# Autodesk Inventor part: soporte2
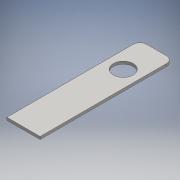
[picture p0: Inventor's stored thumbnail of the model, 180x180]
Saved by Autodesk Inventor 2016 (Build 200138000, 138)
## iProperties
Created: 2016-06
Part Number: soporte2
Material: Genérico
Document SubType Name: Modeling
Designer: adm
Density: 1 g/cm^3
Appearance: Valor por defecto
Author: adm
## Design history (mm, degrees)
sketch "Boceto1"
  geometry: L1 (-25, -100)-(25, -100); L2 (25, -100)-(25, 100); L3 (25, 100)-(-25, 100); L4 (-25, 100)-(-25, -100); L5 (-25, -100)-(25, 100); L6 (25, -100)-(-25, 100); C1 r 15 at (0, 50); 2 further points
  constraints: 12 end point, 2 midpoint, 2 parallel, 1 centre point, 1 coincident, 1 horizontal, 1 perpendicular
  dimensions: "d0" = 50 distance of L3.end L2.end; "d1" = 200 distance of L2.end L1.end; "d2" = 50 distance from line of point (0, 50) L3; "d3" = 30 diameter of C1
extrude "Extrusión1" new body sketch "Boceto1" distance "d4" = 4; taper "d5" = 0 deg
fillet "Empalme1" dims "d6" = 10
node "Sólido1"
